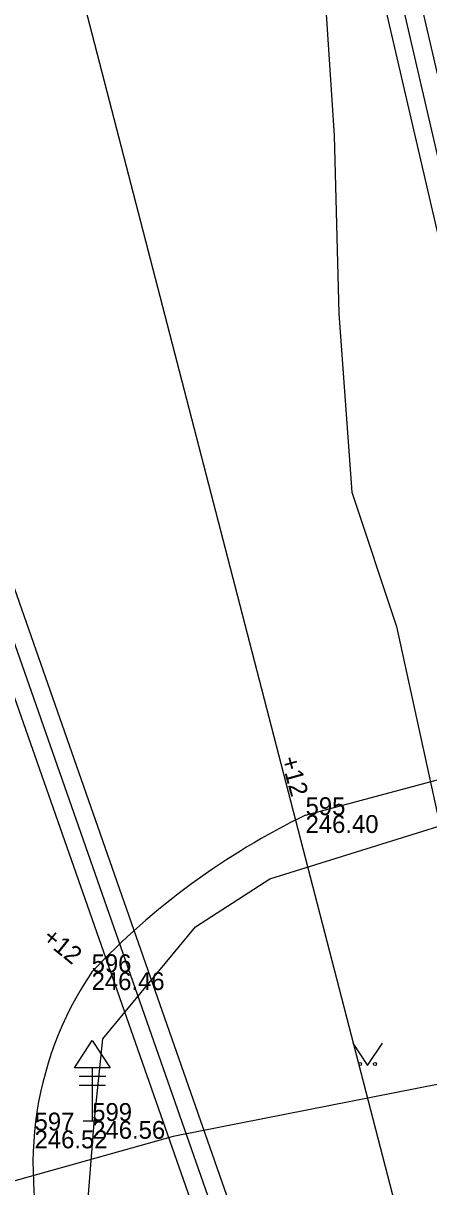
# Model space of a CAD drawing. Extents: x -599432 to -598680, y -1159407 to -1158632.
# Drawn here: x -599222.66 to -599215.84, y -1158968.08 to -1158948.52 of the extents above; entities that cross this region are included whole.
import ezdxf

# ---------------------------------------------------------------- set-up
doc = ezdxf.new("R2010")
doc.units = 0
for name, color, linetype in [('0004 VY - Body podrobné', 7, 'Continuous'), ('0005 VY - Body podrobné - čísla', 7, 'Continuous'), ('0006 VY - Body podrobné - výšky', 7, 'Continuous'), ('0027 ZA - Silnice_cesta zpevněná', 7, 'Continuous'), ('0034 ZA - Kultury - značky', 7, 'Continuous'), ('0057 ZA - Doprava - BKOM buňky', 7, 'Continuous'), ('0073 TE - Výška obrubníků a zdí', 7, 'Continuous'), ('0206 PV - BVK - kanalizace - jednotná', 7, 'Continuous'), ('0211 PV - BVK - kanalizace - jednotná okraj', 7, 'Continuous'), ('0214 PV - BVK - vodovod - pitná', 7, 'Continuous'), ('0552 PV - OT VUT', 7, 'Continuous'), ('0652 PV - BKOM - kabely bez rozlišení', 7, 'Continuous'), ('0653 PV - BKOM - chranička', 7, 'Continuous'), ('0703 PV - DIAL TELECOM optický kabel', 7, 'Continuous')]:
    doc.layers.add(name, color=color, linetype=linetype)

msp = doc.modelspace()

# ---------------------------------------------------------------- linework, layer by layer
at = {"layer": '0004 VY - Body podrobné'}
for p, q in [((-599217.91, -1158961.83), (-599217.91, -1158961.83)), ((-599221.51, -1158964.47), (-599221.51, -1158964.47)), ((-599222.47, -1158967.13), (-599222.47, -1158967.13)), ((-599221.5, -1158966.97), (-599221.5, -1158966.97))]:
    msp.add_line(p, q, dxfattribs=at)
at = {"layer": '0027 ZA - Silnice_cesta zpevněná'}
msp.add_line((-599217.91, -1158961.83), (-599214.411, -1158960.891), dxfattribs=at)
for centre, radius, start, end in [((-599212.477, -1158973.014), 12.434, 115.912, 136.5957), ((-599216.72, -1158967.702), 5.778, 145.9901, 199.7054)]:
    msp.add_arc(centre, radius, start, end, dxfattribs=at)
at = {"layer": '0034 ZA - Kultury - značky'}
msp.add_lwpolyline([(-599217.117, -1158965.663), (-599216.867, -1158966.038), (-599216.617, -1158965.663)], dxfattribs=at)
for centre in [(-599216.992, -1158966.013), (-599216.742, -1158966.013)]:
    msp.add_circle(centre, 0.025, dxfattribs=at)
at = {"layer": '0057 ZA - Doprava - BKOM buňky'}
for p, q in [((-599221.5, -1158966.07), (-599221.5, -1158966.97)), ((-599221.72, -1158966.22), (-599221.272, -1158966.22)), ((-599221.72, -1158966.37), (-599221.277, -1158966.37)), ((-599221.65, -1158966.97), (-599221.35, -1158966.97))]:
    msp.add_line(p, q, dxfattribs=at)
msp.add_lwpolyline([(-599221.8, -1158966.075), (-599221.5, -1158965.62), (-599221.2, -1158966.075)], close=True, dxfattribs=at)
at = {"layer": '0206 PV - BVK - kanalizace - jednotná'}
msp.add_lwpolyline([(-599218.641, -1158970.831), (-599223.869, -1158955.927), (-599224.365, -1158953.57), (-599224.406, -1158951.09), (-599223.997, -1158949.125), (-599223.335, -1158947.745)], dxfattribs=at)
at = {"layer": '0211 PV - BVK - kanalizace - jednotná okraj'}
for points in [[(-599218.924, -1158970.93), (-599224.159, -1158956.008), (-599224.664, -1158953.604), (-599224.707, -1158951.062), (-599224.283, -1158949.028), (-599223.605, -1158947.615)], [(-599223.065, -1158947.875), (-599223.711, -1158949.222), (-599224.105, -1158951.118), (-599224.066, -1158953.536), (-599223.579, -1158955.846), (-599218.358, -1158970.732)]]:
    msp.add_lwpolyline(points, dxfattribs=at)
at = {"layer": '0214 PV - BVK - vodovod - pitná'}
msp.add_lwpolyline([(-599224.534, -1158936.87), (-599222.42, -1158945.16), (-599215.18, -1158973.1), (-599214.01, -1158973.78), (-599152.34, -1158956.416), (-599150.65, -1158955.95), (-599117.576, -1158946.804), (-599098.24, -1158941.96), (-599043.28, -1158926.64)], dxfattribs=at)
at = {"layer": '0552 PV - OT VUT'}
msp.add_lwpolyline([(-599143.93, -1158953.57), (-599144.69, -1158954.41), (-599146.47, -1158953.73), (-599147.68, -1158952.78), (-599149.02, -1158951.66), (-599152.03, -1158949.46), (-599153.86, -1158948.56), (-599170.02, -1158952.91), (-599170.37, -1158953.05), (-599171.41, -1158953.39), (-599171.96, -1158953.52), (-599179.81, -1158955.74), (-599197.67, -1158960.97), (-599213.79, -1158965.98), (-599220.14, -1158967.23), (-599233.22, -1158970.89), (-599235.11, -1158971.48), (-599236.2, -1158971.2), (-599236.635, -1158972.68)], dxfattribs=at)
msp.add_lwpolyline([(-599143.93, -1158953.57), (-599144.69, -1158954.41), (-599146.47, -1158953.73), (-599147.68, -1158952.78), (-599149.02, -1158951.66), (-599152.03, -1158949.46), (-599153.86, -1158948.56), (-599170.02, -1158952.91), (-599170.37, -1158953.05), (-599171.41, -1158953.39), (-599171.96, -1158953.52), (-599179.81, -1158955.74), (-599197.67, -1158960.97), (-599213.79, -1158965.98), (-599220.14, -1158967.23), (-599233.22, -1158970.89), (-599235.11, -1158971.48), (-599236.2, -1158971.2), (-599236.635, -1158972.68)], dxfattribs=at)
at = {"layer": '0652 PV - BKOM - kabely bez rozlišení'}
for points in [[(-599230.59, -1158974.37), (-599220.8, -1158971.75), (-599221.6, -1158968.7), (-599221.47, -1158967), (-599221.32, -1158965.59), (-599219.76, -1158963.71), (-599218.51, -1158962.9), (-599214.91, -1158961.78), (-599213.68, -1158961.96), (-599212.86, -1158962.94), (-599216.66, -1158946.55), (-599217.48, -1158945.68), (-599223.02, -1158942.57)], [(-599234.98, -1158975.02), (-599233.92, -1158975.36), (-599230.92, -1158974.46), (-599230.59, -1158974.37), (-599220.8, -1158971.75), (-599221.6, -1158968.7), (-599221.47, -1158967), (-599221.32, -1158965.59), (-599219.76, -1158963.71), (-599218.51, -1158962.9), (-599214.91, -1158961.78), (-599213.68, -1158961.96), (-599212.86, -1158962.94), (-599216.66, -1158946.55), (-599215.68, -1158946.71), (-599213.41, -1158947.28), (-599210.22, -1158947.13), (-599194.67, -1158942.89)]]:
    msp.add_lwpolyline(points, dxfattribs=at)
at = {"layer": '0653 PV - BKOM - chranička'}
for p, q in [((-599216.952, -1158946.618), (-599213.152, -1158963.008)), ((-599216.368, -1158946.482), (-599212.568, -1158962.872))]:
    msp.add_line(p, q, dxfattribs=at)
at = {"layer": '0703 PV - DIAL TELECOM optický kabel'}
msp.add_lwpolyline([(-599215.74, -1158938.78), (-599216.44, -1158939.68), (-599216.81, -1158942.07), (-599217.62, -1158947.51), (-599217.43, -1158950.41), (-599217.35, -1158953.4), (-599217.13, -1158956.4), (-599216.38, -1158958.66), (-599215.59, -1158962.28)], dxfattribs=at)

# ---------------------------------------------------------------- texts
at = {"layer": '0005 VY - Body podrobné - čísla'}
for s, p in [('595', (-599217.91, -1158961.83)), ('596', (-599221.51, -1158964.47)), ('599', (-599221.5, -1158966.97)), ('597', (-599222.47, -1158967.13))]:
    msp.add_text(s, height=0.3, dxfattribs=at).set_placement(p)
at = {"layer": '0006 VY - Body podrobné - výšky'}
for s, p in [('246.40', (-599217.91, -1158962.13)), ('246.46', (-599221.51, -1158964.77)), ('246.52', (-599222.47, -1158967.43)), ('246.56', (-599221.5, -1158967.27))]:
    msp.add_text(s, height=0.3, dxfattribs=at).set_placement(p)
at = {"layer": '0073 TE - Výška obrubníků a zdí'}
for rotation, p in [(285.5595, (-599218.33, -1158960.884)), (321.2037, (-599222.359, -1158963.929))]:
    msp.add_text('+12', height=0.3, rotation=rotation, dxfattribs=at).set_placement(p)

doc.saveas('drawing.dxf')
